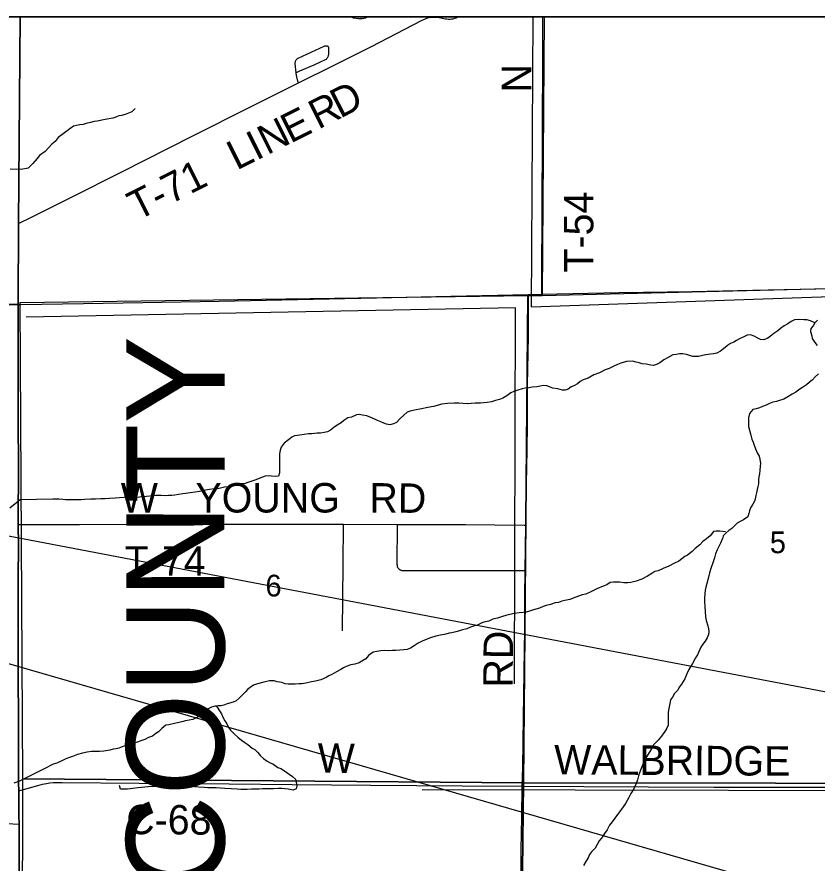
# Model space of a CAD drawing. Extents: x 0 to 34, y 0 to 22.
# Drawn here: x 4.702 to 6.247, y 19.268 to 20.9 of the extents above; entities that cross this region are included whole.
import ezdxf

# ---------------------------------------------------------------- set-up
doc = ezdxf.new("R2010")
doc.units = 0
for name, color, linetype in [('Default', 7, 'Continuous'), ('GM_X_County_Road', 7, 'Continuous'), ('GM_X_County_Road_Text', 7, 'Continuous'), ('GM_X_County_Text', 7, 'Continuous'), ('GM_X_Interstate_Route', 7, 'Continuous'), ('GM_X_Major_River', 7, 'Continuous'), ('GM_X_Minor_River', 7, 'Continuous'), ('GM_X_Section', 7, 'Continuous'), ('GM_X_Section_Text', 7, 'Continuous'), ('GM_X_State_Route', 7, 'Continuous'), ('GM_X_Township_Road', 7, 'Continuous'), ('GM_X_Township_Road_Text', 7, 'Continuous'), ('SH_Data', 7, 'Continuous'), ('SH_Text', 7, 'Continuous')]:
    doc.layers.add(name, color=color, linetype=linetype)

msp = doc.modelspace()

# ---------------------------------------------------------------- linework, layer by layer
at = {"layer": 'Default'}
msp.add_lwpolyline([(4.6471, 20.3461), (4.7052, 20.3461), (4.7053, 20.5025), (4.7088, 20.9), (2.1, 20.9)], dxfattribs=at)
msp.add_lwpolyline([(6.7117, 20.9), (5.7199, 20.9), (5.7161, 20.3629), (6.6624, 20.3857), (6.7136, 20.3867)], close=True, dxfattribs=at)
at = {"layer": 'GM_X_County_Road'}
for p, q in [((4.7055, 20.5019), (4.709, 20.9)), ((4.7054, 20.3456), (4.7055, 20.5019))]:
    msp.add_line(p, q, dxfattribs=at)
for points in [[(4.7054, 19.9211), (4.7053, 19.9492), (4.7056, 20.0082), (4.7053, 20.145), (4.7054, 20.2071), (4.7054, 20.2449), (4.7055, 20.2631), (4.7054, 20.3377), (4.7054, 20.3456)], [(4.7062, 19.4075), (4.7061, 19.4209), (4.7057, 19.4458), (4.7054, 19.7255), (4.7051, 19.8156), (4.7056, 19.8808), (4.7054, 19.9211)], [(4.7062, 19.4075), (4.7104, 19.4087), (4.7429, 19.4178), (4.7517, 19.42), (4.7596, 19.4216), (4.766, 19.4226), (4.7725, 19.4232), (4.7771, 19.4234), (4.7821, 19.4235), (4.7899, 19.4234), (4.9385, 19.4219), (5.1121, 19.4207), (5.2337, 19.4197), (5.3856, 19.4184), (5.5618, 19.417), (5.6777, 19.4164)], [(4.7068, 19.3431), (4.7067, 19.3588), (4.7062, 19.4075)], [(5.6777, 19.4164), (5.7963, 19.4156), (5.9207, 19.4153), (6.0476, 19.4147), (6.1657, 19.4142), (6.2928, 19.4144), (6.4163, 19.4146), (6.5366, 19.4158), (6.6531, 19.4163)], [(4.7056, 18.4179), (4.7057, 18.4951), (4.7057, 18.5354), (4.7055, 18.6193), (4.7054, 18.6659), (4.705, 18.7746), (4.705, 18.8554), (4.7052, 18.8958), (4.7057, 19.0264), (4.7063, 19.0636), (4.7063, 19.1102), (4.7066, 19.1444), (4.7069, 19.2065), (4.707, 19.2687), (4.7072, 19.306), (4.7068, 19.3431)]]:
    msp.add_lwpolyline(points, dxfattribs=at)
at = {"layer": 'GM_X_Interstate_Route'}
for points in [[(4.7066, 19.2071), (4.7068, 19.2692), (4.7069, 19.3065), (4.7066, 19.3437), (4.7064, 19.3593), (4.706, 19.4081), (4.7058, 19.4215), (4.7054, 19.4463), (4.7051, 19.726), (4.7049, 19.8162), (4.7054, 19.8814), (4.7052, 19.9217), (4.7051, 19.9497), (4.7053, 20.0088), (4.7051, 20.1455), (4.7051, 20.2077), (4.7052, 20.2455), (4.7052, 20.2636), (4.7052, 20.3382), (4.7052, 20.3461), (4.7053, 20.5025), (4.7088, 20.9), (2.1, 20.9)], [(8.9, 17.3895), (8.9, 20.9), (4.7088, 20.9), (4.7053, 20.5025), (4.7052, 20.3461), (4.7052, 20.3382), (4.7052, 20.2636), (4.7052, 20.2455), (4.7051, 20.2077), (4.7051, 20.1455), (4.7053, 20.0088), (4.7051, 19.9497), (4.7052, 19.9217), (4.7054, 19.8814), (4.7049, 19.8162), (4.7051, 19.726), (4.7054, 19.4463), (4.7058, 19.4215), (4.706, 19.4081), (4.7064, 19.3593), (4.7066, 19.3437), (4.7069, 19.3065), (4.7068, 19.2692), (4.7066, 19.2071)]]:
    msp.add_lwpolyline(points, dxfattribs=at)
at = {"layer": 'GM_X_Major_River'}
for points in [[(6.2477, 20.3151), (6.2424, 20.3098), (6.239, 20.3045), (6.2348, 20.2992), (6.2337, 20.2935), (6.2363, 20.2851), (6.2374, 20.2798), (6.242, 20.2722), (6.2469, 20.2661)], [(6.2492, 20.2114), (6.2431, 20.2061), (6.237, 20.1993), (6.2313, 20.1951), (6.226, 20.1905)], [(6.226, 20.1905), (6.2188, 20.1852), (6.2131, 20.1818), (6.2055, 20.1765), (6.1987, 20.1727), (6.19, 20.1674), (6.1824, 20.1628), (6.1744, 20.1602), (6.168, 20.1583), (6.1615, 20.1567), (6.1551, 20.1545), (6.1486, 20.1514), (6.1414, 20.1484), (6.1353, 20.1461), (6.1293, 20.1442), (6.1228, 20.1427), (6.116, 20.1351), (6.1141, 20.1271), (6.1145, 20.1184), (6.1145, 20.11), (6.1164, 20.1028), (6.119, 20.0933), (6.1209, 20.0857), (6.1232, 20.08), (6.1251, 20.0743), (6.1277, 20.0667), (6.1308, 20.0595), (6.1346, 20.0527), (6.1364, 20.047), (6.1372, 20.0386), (6.1368, 20.0333), (6.1361, 20.0253), (6.1353, 20.0188), (6.1345, 20.0128), (6.1338, 20.0071), (6.1334, 19.9995), (6.1326, 19.9942), (6.1311, 19.9885), (6.1296, 19.9824), (6.1285, 19.9771), (6.1262, 19.9676), (6.1228, 19.96), (6.1182, 19.9531), (6.1159, 19.9474), (6.1152, 19.9421), (6.1129, 19.936), (6.1045, 19.9303), (6.0981, 19.9269), (6.0924, 19.9235), (6.0875, 19.9182), (6.0818, 19.9136), (6.0761, 19.9094), (6.0708, 19.9041), (6.0651, 19.8992), (6.0646, 19.8954)], [(6.0646, 19.8954), (6.0636, 19.8927), (6.0601, 19.8851), (6.0541, 19.8722), (6.0503, 19.8642), (6.0484, 19.8566), (6.0453, 19.8471), (6.0423, 19.8384), (6.0393, 19.8278), (6.0366, 19.8168), (6.0339, 19.8073), (6.032, 19.8), (6.0309, 19.7943), (6.0294, 19.7799), (6.0294, 19.7716), (6.0297, 19.7628), (6.0309, 19.7533), (6.0316, 19.7427), (6.0328, 19.7362), (6.0358, 19.7256), (6.0369, 19.7203), (6.0377, 19.7146), (6.0373, 19.7089), (6.0347, 19.7024), (6.0309, 19.696), (6.0263, 19.6903), (6.0221, 19.6846), (6.0157, 19.6697), (6.0123, 19.6637), (6.0062, 19.653), (5.9994, 19.6416), (5.9952, 19.6329), (5.9914, 19.6234), (5.9853, 19.6131), (5.9811, 19.6078), (5.9773, 19.601), (5.9717, 19.5949), (5.9675, 19.5881), (5.9637, 19.5827), (5.9625, 19.5759), (5.9606, 19.5664), (5.9595, 19.5592), (5.9595, 19.5413), (5.9591, 19.5341), (5.9568, 19.5284), (5.953, 19.522), (5.9462, 19.5128), (5.9398, 19.5053), (5.931, 19.4961), (5.9269, 19.4882), (5.9196, 19.4764), (5.9143, 19.4676), (5.9109, 19.4604), (5.9071, 19.4502), (5.9041, 19.4418), (5.9018, 19.4365), (5.8999, 19.4289), (5.8976, 19.4217), (5.8927, 19.4114), (5.8874, 19.4023), (5.8836, 19.3947), (5.8771, 19.3829), (5.8691, 19.3719), (5.8631, 19.3643), (5.8566, 19.3548), (5.8509, 19.3476), (5.846, 19.3415), (5.8418, 19.3324), (5.8361, 19.3248), (5.8323, 19.3187), (5.8263, 19.3108), (5.8183, 19.2967), (5.8111, 19.2899), (5.8073, 19.2845), (5.8046, 19.2781), (5.8004, 19.2709), (5.7959, 19.2633)]]:
    msp.add_lwpolyline(points, dxfattribs=at)
at = {"layer": 'GM_X_Minor_River'}
for points in [[(5.3792, 20.9), (5.3752, 20.8977), (5.3687, 20.8965), (5.3619, 20.8962), (5.352, 20.8977), (5.3469, 20.9)], [(5.6979, 20.9), (5.6949, 20.3407), (6.497, 20.3683), (6.5391, 20.3599)], [(4.9308, 20.7234), (4.924, 20.7169), (4.9179, 20.7143), (4.9114, 20.7116), (4.9046, 20.7101), (4.8993, 20.709), (4.8932, 20.7067), (4.8879, 20.7048), (4.8727, 20.7021), (4.8572, 20.6987), (4.8515, 20.698), (4.8443, 20.6961), (4.8359, 20.6942), (4.8302, 20.6926), (4.8242, 20.6919), (4.8173, 20.6907), (4.812, 20.6896), (4.8048, 20.6839), (4.7968, 20.6786), (4.7915, 20.6748), (4.7824, 20.6672), (4.7764, 20.6596), (4.7699, 20.6547), (4.757, 20.6406), (4.746, 20.633), (4.7413, 20.6269), (4.7333, 20.6176), (4.7241, 20.6084), (4.7104, 20.6055)], [(4.7104, 20.6055), (4.6895, 20.6065)], [(5.6628, 19.6136), (5.6649, 20.3392), (4.7205, 20.3211)], [(6.2424, 20.3098), (6.2337, 20.314), (6.2268, 20.3155), (6.2208, 20.3159), (6.2113, 20.3163), (6.2029, 20.3155), (6.1969, 20.3129), (6.19, 20.3083), (6.1828, 20.3041), (6.176, 20.2988), (6.1707, 20.2943), (6.1631, 20.2893), (6.157, 20.2844), (6.1513, 20.2802), (6.1437, 20.2772), (6.1377, 20.2776), (6.132, 20.2806), (6.1251, 20.284), (6.1179, 20.2867), (6.1115, 20.2863), (6.105, 20.2833), (6.0971, 20.2791), (6.0914, 20.2757), (6.0857, 20.273), (6.0796, 20.2704), (6.0739, 20.2666), (6.0659, 20.2601), (6.0602, 20.2555), (6.0534, 20.2517), (6.047, 20.2502), (6.0409, 20.2495), (6.0322, 20.2483), (6.0253, 20.2468), (6.0177, 20.2453), (6.0071, 20.2453), (6.0007, 20.2468), (5.9946, 20.2487), (5.9878, 20.2499), (5.9813, 20.2499), (5.9745, 20.2491), (5.9684, 20.248), (5.9578, 20.2426), (5.951, 20.2388), (5.9434, 20.2331), (5.9369, 20.2294), (5.9312, 20.2278), (5.9259, 20.2286), (5.9168, 20.2301), (5.9088, 20.2309), (5.9032, 20.2328), (5.8978, 20.2343), (5.8906, 20.2358), (5.8789, 20.2354), (5.8682, 20.2324), (5.8618, 20.2297), (5.8546, 20.2263), (5.8451, 20.2221), (5.8375, 20.2195), (5.8265, 20.2134), (5.8159, 20.2096), (5.8049, 20.2032), (5.7954, 20.2001), (5.7893, 20.1967), (5.784, 20.1925), (5.7772, 20.1887), (5.7719, 20.1864), (5.7662, 20.1823), (5.7608, 20.18), (5.7555, 20.1804), (5.7461, 20.1827), (5.7369, 20.1842), (5.7252, 20.1884), (5.7187, 20.1891), (5.7055, 20.1868), (5.6971, 20.1861), (5.6903, 20.1846), (5.6834, 20.1842), (5.6778, 20.183), (5.669, 20.1804), (5.6614, 20.1774), (5.6554, 20.1751), (5.6478, 20.1694), (5.6402, 20.1648), (5.6337, 20.1622), (5.6261, 20.1599), (5.6182, 20.1576), (5.6102, 20.1561), (5.5973, 20.1549), (5.5867, 20.1549), (5.5715, 20.1538), (5.5628, 20.1546), (5.5552, 20.155), (5.5461, 20.1553), (5.5332, 20.1546), (5.5226, 20.1534), (5.5066, 20.1489), (5.4956, 20.147), (5.4835, 20.1439), (5.4698, 20.1417), (5.4615, 20.1394), (5.4558, 20.1375)], [(5.4558, 20.1375), (5.4489, 20.1322), (5.4417, 20.125), (5.4353, 20.1181), (5.4292, 20.1155), (5.422, 20.1136), (5.4159, 20.1143), (5.4106, 20.1166), (5.4049, 20.1189), (5.3985, 20.1216), (5.3886, 20.1261), (5.3776, 20.1307), (5.3693, 20.1318), (5.3632, 20.133), (5.3579, 20.1326), (5.3484, 20.128), (5.3412, 20.1265), (5.3336, 20.1219), (5.3283, 20.1174), (5.3203, 20.1124), (5.3139, 20.1079), (5.3074, 20.103), (5.3021, 20.0999), (5.2956, 20.0984), (5.2881, 20.0973), (5.2816, 20.0969), (5.2714, 20.0961), (5.2653, 20.0957), (5.2569, 20.0946), (5.2482, 20.0935), (5.238, 20.0923), (5.2327, 20.0893), (5.2266, 20.0843), (5.2182, 20.0779), (5.2125, 20.0703), (5.2103, 20.0646), (5.2095, 20.0574), (5.2095, 20.0281), (5.2091, 20.0209), (5.2072, 20.0144), (5.2011, 20.0137), (5.1939, 20.0141), (5.1879, 20.0148), (5.1818, 20.0141), (5.1765, 20.0122), (5.1712, 20.0107), (5.1636, 20.0069), (5.1556, 20.0046), (5.1484, 20.0023), (5.1427, 20.0004), (5.1359, 19.9993), (5.1249, 19.9966), (5.1177, 19.9958), (5.1112, 19.9936), (5.1029, 19.9928), (5.0926, 19.9905), (5.0839, 19.9898), (5.074, 19.9883), (5.0661, 19.9871), (5.0547, 19.9845), (5.0467, 19.9837), (5.0368, 19.9822), (5.0281, 19.981), (5.0224, 19.9803), (5.0141, 19.9791), (5.0072, 19.9776), (5.0016, 19.9772), (4.9947, 19.9769), (4.9883, 19.9765), (4.9807, 19.9769), (4.9704, 19.9769), (4.9647, 19.9765), (4.9526, 19.975), (4.9454, 19.9746), (4.9389, 19.9735), (4.9325, 19.9731), (4.9257, 19.9735), (4.9177, 19.9735), (4.8919, 19.9719), (4.8813, 19.9712), (4.8729, 19.9708), (4.8642, 19.9704), (4.854, 19.9701), (4.8452, 19.9701), (4.8327, 19.9693), (4.8263, 19.9689), (4.8156, 19.9689), (4.8092, 19.9689), (4.7963, 19.9689), (4.791, 19.9693), (4.7841, 19.9697), (4.7784, 19.9701), (4.7716, 19.9697), (4.7087, 19.9685)], [(4.7087, 19.9685), (4.6885, 19.9528)], [(6.0702, 19.9069), (6.059, 19.9079), (6.0522, 19.9083), (6.0469, 19.9076), (6.04, 19.8992), (6.0332, 19.8931), (6.0264, 19.8882), (6.0203, 19.8821), (6.0112, 19.8745), (6.0055, 19.8688), (5.9968, 19.862), (5.9911, 19.8593), (5.9801, 19.8506), (5.9713, 19.8468), (5.9607, 19.8407), (5.9497, 19.8365), (5.9398, 19.832), (5.9334, 19.8301), (5.9277, 19.8267), (5.9194, 19.8213), (5.9083, 19.8156), (5.8973, 19.8115), (5.8875, 19.8092), (5.8814, 19.8084), (5.8734, 19.8088), (5.8651, 19.8096), (5.8537, 19.81), (5.8476, 19.8092), (5.8412, 19.805), (5.8336, 19.802), (5.8214, 19.7967), (5.8116, 19.7917), (5.8006, 19.7868), (5.7934, 19.7853), (5.7812, 19.7807), (5.7698, 19.7765), (5.76, 19.7743), (5.7543, 19.7731), (5.7475, 19.7708), (5.741, 19.7697), (5.7323, 19.7667), (5.7236, 19.7648), (5.7179, 19.7629), (5.711, 19.7594), (5.6996, 19.7564), (5.6917, 19.7538), (5.6852, 19.7522), (5.6795, 19.7515), (5.6716, 19.7507), (5.6621, 19.7496), (5.6568, 19.7484), (5.6477, 19.7462), (5.6374, 19.7431), (5.6298, 19.7405), (5.6207, 19.7382), (5.6131, 19.7348), (5.6036, 19.7325), (5.5983, 19.731), (5.5923, 19.7276), (5.5835, 19.7253), (5.5778, 19.723), (5.571, 19.72), (5.5623, 19.7181), (5.5566, 19.7162), (5.5494, 19.7139), (5.5418, 19.7124), (5.5365, 19.7112), (5.5304, 19.7093), (5.5202, 19.7078), (5.5111, 19.7059), (5.5008, 19.7025), (5.486, 19.6968), (5.4769, 19.6922), (5.4689, 19.6869), (5.4621, 19.6827), (5.4553, 19.6801), (5.4492, 19.6793), (5.4416, 19.679), (5.4336, 19.6782), (5.4264, 19.6778), (5.4188, 19.6774), (5.4109, 19.6778), (5.4048, 19.6774), (5.3968, 19.6763), (5.39, 19.6748), (5.3809, 19.6683), (5.3756, 19.6622), (5.3684, 19.6573), (5.3631, 19.6543), (5.3547, 19.6516), (5.3471, 19.6501), (5.338, 19.6474), (5.3327, 19.6444), (5.3274, 19.6417), (5.3194, 19.6372), (5.3099, 19.6315), (5.3046, 19.6292), (5.2993, 19.6258), (5.2887, 19.6216), (5.2788, 19.619), (5.2712, 19.6174)], [(5.2712, 19.6174), (5.2602, 19.6152), (5.2523, 19.614), (5.2466, 19.6136), (5.2394, 19.6129), (5.2261, 19.6129), (5.22, 19.6136), (5.2136, 19.6163), (5.2048, 19.6178), (5.1988, 19.6197), (5.19, 19.6193), (5.179, 19.6167), (5.1669, 19.614), (5.1593, 19.611), (5.1479, 19.6034), (5.1437, 19.5981), (5.1384, 19.5931), (5.1316, 19.5859), (5.1255, 19.581), (5.1198, 19.5783), (5.1084, 19.5749), (5.102, 19.5726), (5.0967, 19.5715), (5.091, 19.5711), (5.0849, 19.5707), (5.0781, 19.5688), (5.0713, 19.5658), (5.0652, 19.5628), (5.0614, 19.5571), (5.0538, 19.5506), (5.0485, 19.5479), (5.042, 19.5449), (5.0352, 19.5434), (5.0276, 19.5422), (5.0208, 19.5407), (5.0121, 19.5384), (5.0064, 19.5373), (4.9954, 19.535), (4.9901, 19.5339), (4.9821, 19.5278), (4.976, 19.5214), (4.9707, 19.5179), (4.9639, 19.5126), (4.9567, 19.51), (4.9495, 19.5065), (4.9419, 19.5039), (4.9206, 19.4963), (4.913, 19.4948), (4.9054, 19.4925), (4.8994, 19.4898), (4.8941, 19.4887), (4.888, 19.4876), (4.8815, 19.486), (4.8701, 19.4838), (4.8618, 19.4834), (4.8553, 19.4834), (4.8462, 19.483), (4.8383, 19.4822), (4.8292, 19.48), (4.8193, 19.4777), (4.8098, 19.4739), (4.8018, 19.4709), (4.7954, 19.4686), (4.7893, 19.4652), (4.7798, 19.461), (4.7726, 19.4587), (4.7673, 19.456), (4.7601, 19.4526), (4.7073, 19.4258)], [(5.0872, 19.5709), (5.0887, 19.5688), (5.0936, 19.562), (5.0974, 19.5559), (5.1001, 19.5498), (5.1039, 19.5422), (5.1073, 19.5365), (5.1107, 19.5297), (5.1149, 19.5244), (5.1217, 19.5172), (5.1289, 19.5111), (5.1357, 19.5054), (5.1422, 19.5008), (5.1483, 19.4966), (5.1566, 19.4898), (5.1619, 19.4868), (5.1672, 19.4811), (5.1725, 19.4746), (5.1782, 19.4697), (5.1851, 19.4643), (5.1911, 19.4617), (5.1964, 19.4594), (5.2059, 19.4526), (5.2116, 19.4507), (5.2188, 19.4461), (5.2279, 19.4396), (5.234, 19.4351), (5.2401, 19.4298), (5.2416, 19.4233), (5.2427, 19.4172), (5.2416, 19.4115), (5.2355, 19.4089), (5.226, 19.4104), (5.2192, 19.4115), (5.2135, 19.4119), (5.2067, 19.4119), (5.1976, 19.4115), (5.1915, 19.4115), (5.1832, 19.4112), (5.1763, 19.4112), (5.1699, 19.4108), (5.1646, 19.4108), (5.1555, 19.4104), (5.1467, 19.41), (5.1414, 19.41), (5.1346, 19.41), (5.1274, 19.4108), (5.116, 19.4112), (5.1039, 19.4119), (5.0951, 19.4127), (5.0872, 19.4131), (5.0811, 19.4134), (5.0712, 19.4134), (5.0636, 19.4138), (5.0526, 19.4146), (5.0454, 19.415), (5.0359, 19.4169), (5.0287, 19.4173), (5.017, 19.4173), (5.0071, 19.4169), (4.995, 19.4161), (4.9794, 19.4161), (4.9718, 19.4157), (4.9559, 19.415), (4.9491, 19.4146), (4.943, 19.4138), (4.9361, 19.4131), (4.9263, 19.4116), (4.9157, 19.4108), (4.9024, 19.4108), (4.9005, 19.4176)], [(4.7073, 19.4258), (4.6968, 19.4222)], [(6.9619, 19.4063), (5.4848, 19.4092)]]:
    msp.add_lwpolyline(points, dxfattribs=at)
at = {"layer": 'GM_X_Section'}
for points in [[(6.6624, 20.3857), (6.6525, 19.4215), (5.6799, 19.4229), (5.6885, 20.3628), (5.7161, 20.3629)], [(5.6885, 20.3628), (5.6799, 19.4229), (4.7138, 19.4306), (4.7085, 20.3491)], [(4.7138, 19.4306), (5.6799, 19.4229), (5.6682, 18.408), (4.7098, 18.4163), (4.714, 19.3507)], [(5.6799, 19.4229), (6.6525, 19.4215), (6.6382, 18.4059), (5.6682, 18.408)]]:
    msp.add_lwpolyline(points, close=True, dxfattribs=at)
at = {"layer": 'GM_X_State_Route'}
msp.add_line((5.6897, 20.3645), (5.7156, 20.365), dxfattribs=at)
for points in [[(5.7156, 20.365), (5.8647, 20.3682), (6.0052, 20.3707), (6.1521, 20.3737), (6.306, 20.3769), (6.3093, 20.3769), (6.3599, 20.378), (6.4339, 20.38), (6.4792, 20.3805), (6.5002, 20.3799), (6.5174, 20.3787), (6.5333, 20.3772)], [(4.7054, 20.3456), (4.7102, 20.3456), (4.8309, 20.3476), (4.9455, 20.349), (5.0927, 20.3518), (5.2439, 20.3547), (5.3964, 20.358), (5.54, 20.3615), (5.6897, 20.3645)], [(4.678, 20.3456), (4.7054, 20.3456)]]:
    msp.add_lwpolyline(points, dxfattribs=at)
at = {"layer": 'GM_X_Township_Road'}
for p, q in [((5.6897, 20.3645), (5.7156, 20.365)), ((5.3329, 19.9215), (5.4372, 19.9212)), ((5.6834, 19.8325), (5.6849, 19.9195))]:
    msp.add_line(p, q, dxfattribs=at)
for points in [[(5.2456, 20.7726), (5.3146, 20.8071), (5.3866, 20.8432), (5.4835, 20.8929), (5.4888, 20.8956), (5.4921, 20.8971), (5.4948, 20.8981), (5.4978, 20.899), (5.5012, 20.8995), (5.5045, 20.8997), (5.5079, 20.8998), (5.511, 20.8997), (5.514, 20.8994), (5.5203, 20.8984), (5.5294, 20.8965), (5.5324, 20.896), (5.5354, 20.8957), (5.5385, 20.8957), (5.5414, 20.896), (5.5444, 20.8965), (5.5473, 20.8974), (5.5501, 20.8985), (5.5529, 20.9)], [(5.7156, 20.365), (5.7161, 20.5593), (5.7165, 20.6402), (5.7168, 20.7242), (5.7171, 20.7802), (5.7173, 20.8642), (5.7174, 20.9)], [(5.2412, 20.7924), (5.2395, 20.8101), (5.2396, 20.8118), (5.2398, 20.8133), (5.2401, 20.8147), (5.2407, 20.8162), (5.2416, 20.8174), (5.2425, 20.8185), (5.2437, 20.8195), (5.245, 20.8202), (5.2951, 20.8436), (5.2966, 20.8441), (5.298, 20.8445), (5.2994, 20.8445), (5.3001, 20.8445), (5.3008, 20.8444), (5.3014, 20.8441), (5.3021, 20.8438), (5.3026, 20.8433), (5.3029, 20.8428), (5.3033, 20.8421), (5.3035, 20.8415), (5.3037, 20.8397), (5.3036, 20.8277), (5.3034, 20.8259), (5.3031, 20.8242), (5.3026, 20.8229), (5.3019, 20.8215), (5.3011, 20.8203), (5.3001, 20.819), (5.299, 20.818), (5.2973, 20.817), (5.2756, 20.807), (5.2479, 20.7951), (5.2412, 20.7924)], [(5.2456, 20.7726), (5.2447, 20.7759), (5.2424, 20.7846), (5.2418, 20.7877), (5.2413, 20.7911), (5.2412, 20.7924)], [(4.7055, 20.5019), (4.708, 20.503), (4.7148, 20.5059), (4.7231, 20.5097), (4.8063, 20.5517), (4.9036, 20.6007), (5.0418, 20.6704), (5.1506, 20.7252), (5.2255, 20.7625), (5.2456, 20.7726)], [(5.6849, 19.9195), (5.6851, 19.9345), (5.6861, 19.9998), (5.6871, 20.0651), (5.6877, 20.1148), (5.688, 20.1895), (5.6893, 20.2516), (5.6897, 20.2858), (5.6897, 20.3645)], [(4.7054, 19.9211), (4.8234, 19.9212), (4.9495, 19.9214), (5.0444, 19.9215)], [(5.0444, 19.9215), (5.0713, 19.9215), (5.1975, 19.9217), (5.3329, 19.9215)], [(5.3308, 19.7163), (5.3321, 19.843), (5.3329, 19.9215)], [(5.4396, 19.8353), (5.4387, 19.8362), (5.4382, 19.837), (5.4376, 19.838), (5.4372, 19.8387), (5.437, 19.8396), (5.4368, 19.8406), (5.4367, 19.8418), (5.4366, 19.8439), (5.4372, 19.9212)], [(5.4372, 19.9212), (5.4549, 19.9211), (5.5681, 19.9208), (5.6811, 19.9195), (5.6849, 19.9195)], [(5.4396, 19.8353), (5.4406, 19.8344), (5.4414, 19.8339), (5.4425, 19.8334), (5.4433, 19.833), (5.4442, 19.8327), (5.4452, 19.8325), (5.4465, 19.8324), (5.4495, 19.8322), (5.4969, 19.8324), (5.6128, 19.8325), (5.6834, 19.8325)], [(5.6777, 19.4164), (5.6786, 19.4525), (5.6802, 19.5489), (5.6823, 19.6795), (5.6825, 19.7168), (5.6824, 19.7822), (5.6834, 19.8325)], [(5.6652, 18.4079), (5.6658, 18.4202), (5.6666, 18.5074), (5.6671, 18.5446), (5.6681, 18.613), (5.6685, 18.7312), (5.6691, 18.8462), (5.6696, 18.9239), (5.6702, 19.0016), (5.6707, 19.0607), (5.6714, 19.0825), (5.6728, 19.1291), (5.6736, 19.1633), (5.6742, 19.2037), (5.6753, 19.2597), (5.6758, 19.2939), (5.677, 19.3561), (5.6777, 19.4164)], [(4.2028, 19.372), (4.2303, 19.3704), (4.2762, 19.3679), (4.342, 19.3639), (4.3717, 19.362), (4.3972, 19.3606), (4.4437, 19.3583), (4.5056, 19.355), (4.5242, 19.354), (4.5682, 19.3511), (4.5999, 19.3493), (4.6216, 19.3483), (4.6943, 19.3439), (4.7068, 19.3431)]]:
    msp.add_lwpolyline(points, dxfattribs=at)
at = {"layer": 'SH_Data'}
msp.add_line((2.1, 20.9), (8.9, 20.9), dxfattribs=at)
at = {"layer": 'SH_Text'}
msp.add_lwpolyline([(9.2181, 19.0346), (2.1904, 20.3744), (9.2181, 18.3428)], close=True, dxfattribs=at)

# ---------------------------------------------------------------- texts
at = {"layer": 'GM_X_County_Road_Text'}
for s, height, rotation, p in [('W', 0.0568, 359.2752, (5.2824, 19.4425)), ('WALBRIDGE', 0.05682, 359.6575, (5.739, 19.4392)), ('C-68', 0.05682, 359.6571, (4.9132, 19.3239))]:
    msp.add_text(s, height=height, rotation=rotation, dxfattribs=at).set_placement(p)
at = {"layer": 'GM_X_County_Text'}
msp.add_text('OTTAWA COUNTY', height=0.189394, rotation=89.9764, dxfattribs=at).set_placement((5.1023, 18.0616))
at = {"layer": 'GM_X_Section_Text'}
for s, p in [('5', (6.1554, 19.8657)), ('6', (5.1821, 19.7823))]:
    msp.add_text(s, height=0.0419, rotation=0, dxfattribs=at).set_placement(p)
at = {"layer": 'GM_X_Township_Road_Text'}
for s, height, rotation, p in [('N', 0.0568, 90, (5.695, 20.7543)), ('D', 0.0568, 27.2413, (5.3262, 20.7035)), ('R', 0.0568, 26.658, (5.284, 20.6823)), ('E', 0.0568, 26.5743, (5.2302, 20.6554)), ('N', 0.0568, 26.5602, (5.1855, 20.6331)), ('I', 0.0568, 26.5659, (5.1646, 20.6226)), ('L', 0.0568, 26.565, (5.1266, 20.6036)), ('T-71', 0.05682, 26.7225, (4.9348, 20.5062)), ('T-54', 0.05682, 90, (5.8149, 20.4068)), ('W', 0.0568, 0, (4.9029, 19.9442)), ('YOUNG', 0.05682, 0, (5.0471, 19.9442)), ('RD', 0.05682, 359.5053, (5.3825, 19.9442)), ('T-74', 0.05682, 0, (4.9104, 19.8224)), ('RD', 0.05682, 89.5135, (5.6591, 19.6063))]:
    msp.add_text(s, height=height, rotation=rotation, dxfattribs=at).set_placement(p)

doc.saveas('drawing.dxf')
